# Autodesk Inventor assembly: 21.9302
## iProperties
Created: 2011-01
Part Number: 21.9302
Document SubType Name: Assembly
Designer: Administrator
Description: LEVER HANDLE NON-LOCKING
Author: Administrator
